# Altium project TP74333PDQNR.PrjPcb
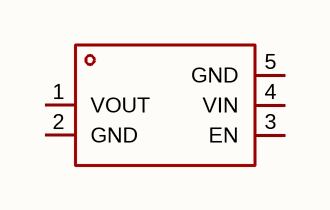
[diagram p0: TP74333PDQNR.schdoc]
1 sheet, 1 parts. Net scope: global (net labels, ports and power ports of the same name join across sheets).

## Sheet TP74333PDQNR.schdoc
size 127 x 101 mm

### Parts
U?  tp74333pdqnr  [XDFN-4_L1.0-W1.0-P0.65-BL-EP]  (value not drawn)

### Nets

Not connected (* = marked no-connect by the designer): U? 1(VOUT) 2(GND) 3(EN) 4(VIN) 5(GND)

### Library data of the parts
U? = tp74333pdqnr: 输出极性:正极;工作电压:5.5V;输出电压:3.3V;输出电流:300mA;电源纹波抑制比(PSRR):75dB@(1kHz);输出类型:固定;; Manufacturer: TECH PUBLIC(台舟); AddInBom: yes; ModelId: 0095c5b582f64c2fb25ce9a94c122b3a; ModelName: XDFN-4_L1.0-W1.0-H0.6-P0.65-BL-EP; ModelTransform: 39.37,40.1574,0,0,0,0,0.005,-0.005,0; Output Configuration: 正极; Voltage - Supply: 5.5V; Output Voltage: 3.3V; Output Current: 300mA; Voltage Dropout: 200mV@(300mA); standby current: 8uA; Noise: 51uVrms; Output Type: 固定; Number of Outputs: 1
